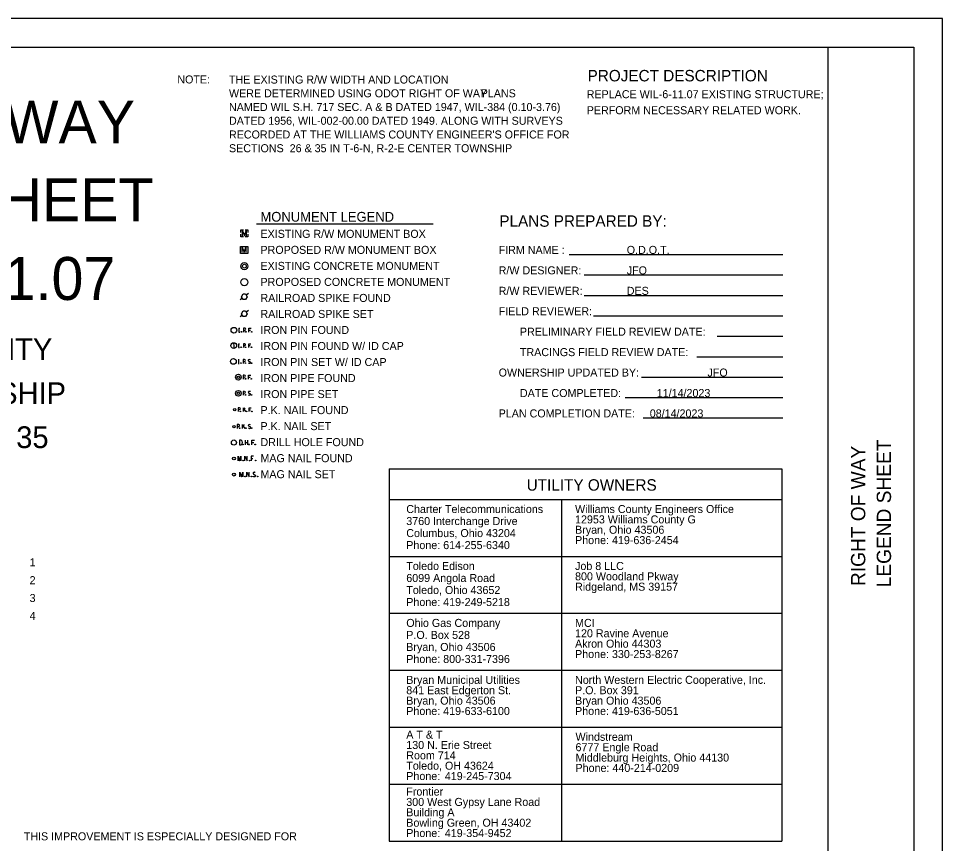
# Model space of a CAD drawing. Extents: x 0 to 34, y 0 to 22.
# Drawn here: x 17.84 to 34, y 7.58 to 22 of the extents above; entities that cross this region are included whole.
import ezdxf

# ---------------------------------------------------------------- set-up
doc = ezdxf.new("R2010")
doc.units = 0
for name, color, linetype in [('SH_Border', 7, 'Continuous'), ('SH_Cut_Line', 7, 'Continuous'), ('SH_Data', 7, 'Continuous'), ('SH_Text', 7, 'Continuous'), ('SV_P_Control_Cells_Set', 7, 'Continuous'), ('SV_X_Control_Cells_Found', 7, 'Continuous')]:
    doc.layers.add(name, color=color, linetype=linetype)

msp = doc.modelspace()

# ---------------------------------------------------------------- linework, layer by layer
at = {"layer": 'SH_Border'}
msp.add_line((32, 0.5), (32, 21.5), dxfattribs=at)
msp.add_lwpolyline([(1.5, 21.5), (33.5, 21.5), (33.5, 0.5), (1.5, 0.5)], close=True, dxfattribs=at)
at = {"layer": 'SH_Cut_Line'}
msp.add_lwpolyline([(0, 0), (34, 0), (34, 22), (0, 22)], close=True, dxfattribs=at)
at = {"layer": 'SH_Text'}
for p, q in [((22.005, 18.412), (25.097, 18.412)), ((21.793, 18.246), (21.793, 18.246)), ((21.788, 17.956), (21.788, 17.956)), ((27.471, 17.876), (31.208, 17.876)), ((27.735, 17.519), (31.208, 17.519)), ((21.866, 17.194), (21.826, 17.164)), ((27.735, 17.162), (31.208, 17.162)), ((21.759, 17.114), (21.719, 17.084)), ((21.759, 16.817), (21.719, 16.787)), ((21.866, 16.897), (21.826, 16.867)), ((27.899, 16.804), (31.208, 16.804)), ((21.694, 16.587), (21.711, 16.587)), ((21.694, 16.587), (21.711, 16.587)), ((21.694, 16.52), (21.711, 16.52)), ((21.703, 16.52), (21.703, 16.587)), ((21.779, 16.555), (21.806, 16.555)), ((21.873, 16.52), (21.873, 16.587)), ((21.873, 16.587), (21.911, 16.587)), ((21.873, 16.554), (21.9, 16.554)), ((30.062, 16.447), (31.208, 16.447)), ((21.607, 16.289), (21.607, 16.252)), ((21.69, 16.317), (21.707, 16.317)), ((21.69, 16.317), (21.707, 16.317)), ((21.69, 16.251), (21.707, 16.251)), ((21.698, 16.251), (21.698, 16.317)), ((21.775, 16.285), (21.802, 16.285)), ((21.869, 16.251), (21.869, 16.317)), ((21.869, 16.317), (21.907, 16.317)), ((21.869, 16.285), (21.896, 16.285)), ((21.686, 16.041), (21.702, 16.041)), ((21.686, 16.041), (21.702, 16.041)), ((21.694, 15.974), (21.694, 16.041)), ((21.771, 16.009), (21.797, 16.009)), ((21.865, 16.017), (21.895, 16.001)), ((29.705, 16.09), (31.208, 16.09)), ((21.686, 15.974), (21.702, 15.974)), ((21.772, 15.733), (21.798, 15.733)), ((21.865, 15.699), (21.865, 15.765)), ((21.865, 15.765), (21.904, 15.765)), ((21.865, 15.733), (21.893, 15.733)), ((28.735, 15.733), (31.208, 15.733)), ((21.772, 15.452), (21.798, 15.452)), ((21.866, 15.46), (21.897, 15.444)), ((28.45, 15.375), (31.208, 15.375)), ((21.777, 15.13), (21.777, 15.197)), ((21.777, 15.154), (21.809, 15.197)), ((21.875, 15.13), (21.875, 15.197)), ((21.875, 15.197), (21.914, 15.197)), ((21.684, 15.165), (21.71, 15.165)), ((21.787, 15.168), (21.815, 15.13)), ((21.875, 15.164), (21.903, 15.164)), ((21.669, 14.872), (21.696, 14.872)), ((21.762, 14.837), (21.762, 14.904)), ((21.762, 14.861), (21.794, 14.904)), ((21.772, 14.875), (21.8, 14.837)), ((21.868, 14.88), (21.898, 14.864)), ((28.765, 15.019), (31.208, 15.019)), ((24.323, 14.128), (31.19, 14.128)), ((24.323, 14.128), (24.323, 7.625)), ((31.19, 14.128), (31.19, 7.625)), ((24.323, 13.597), (31.19, 13.597)), ((27.34, 13.597), (27.34, 7.625)), ((24.323, 12.601), (31.19, 12.601)), ((24.323, 11.606), (31.19, 11.606)), ((24.323, 10.611), (31.19, 10.611)), ((24.323, 9.616), (31.19, 9.616)), ((24.323, 8.621), (31.19, 8.621)), ((24.323, 7.625), (31.19, 7.625))]:
    msp.add_line(p, q, dxfattribs=at)
for points in [[(21.73, 18.262), (21.73, 18.309), (21.777, 18.309)], [(21.762, 18.204), (21.762, 18.288), (21.793, 18.204), (21.823, 18.288), (21.823, 18.204)], [(21.807, 18.309), (21.855, 18.309), (21.855, 18.262)], [(21.777, 18.184), (21.73, 18.184), (21.73, 18.23)], [(21.855, 18.23), (21.855, 18.184), (21.807, 18.184)], [(21.725, 18.018), (21.851, 18.018), (21.851, 17.893), (21.725, 17.893), (21.725, 18.018)], [(21.757, 17.914), (21.757, 17.997), (21.788, 17.914), (21.819, 17.997), (21.819, 17.914)], [(21.806, 16.587), (21.779, 16.587), (21.779, 16.52)], [(21.802, 16.317), (21.775, 16.317), (21.775, 16.251)], [(21.797, 16.041), (21.771, 16.041), (21.771, 15.974)], [(21.798, 15.765), (21.772, 15.765), (21.772, 15.699)], [(21.798, 15.484), (21.772, 15.484), (21.772, 15.417)], [(21.71, 15.197), (21.684, 15.197), (21.684, 15.13)], [(21.696, 14.904), (21.669, 14.904), (21.669, 14.837)]]:
    msp.add_lwpolyline(points, dxfattribs=at)
for points in [[(21.774, 17.189), (21.811, 17.189), (21.841, 17.139), (21.811, 17.089), (21.774, 17.089), (21.744, 17.139)], [(21.774, 16.892), (21.811, 16.892), (21.841, 16.842), (21.811, 16.792), (21.774, 16.792), (21.744, 16.842)]]:
    msp.add_lwpolyline(points, close=True, dxfattribs=at)
for centre, radius in [((21.793, 17.673), 0.0625), ((21.793, 17.673), 0.0333), ((21.793, 17.392), 0.0625), ((21.611, 16.553), 0.05), ((21.743, 16.524), 0.00583), ((21.819, 16.524), 0.00583), ((21.921, 16.524), 0.00583), ((21.607, 16.284), 0.05), ((21.607, 16.311), 0.00667), ((21.738, 16.255), 0.00583), ((21.815, 16.255), 0.00583), ((21.917, 16.255), 0.00583), ((21.602, 16.008), 0.05), ((21.734, 15.979), 0.00583), ((21.811, 15.979), 0.00583), ((21.918, 15.978), 0.00583), ((21.688, 15.732), 0.05), ((21.688, 15.732), 0.0206), ((21.812, 15.703), 0.00583), ((21.914, 15.703), 0.00583), ((21.688, 15.45), 0.05), ((21.688, 15.45), 0.0208), ((21.812, 15.422), 0.00583), ((21.919, 15.421), 0.00583), ((21.624, 15.163), 0.0207), ((21.724, 15.134), 0.00583), ((21.833, 15.134), 0.00583), ((21.924, 15.134), 0.00583), ((21.611, 14.87), 0.0206), ((21.71, 14.842), 0.00583), ((21.821, 14.842), 0.00583), ((21.921, 14.842), 0.00583)]:
    msp.add_circle(centre, radius, dxfattribs=at)
for centre, radius, start, end in [((21.803, 16.571), 0.0162, 278.8803, 81.1197), ((21.799, 16.301), 0.0162, 278.8803, 81.1197), ((21.795, 16.025), 0.0162, 278.8803, 81.1197), ((21.871, 16.027), 0.0118, 126.2587, 236.3675), ((21.881, 16.006), 0.0349, 61.3463, 118.6537), ((21.886, 15.99), 0.0148, 311.4883, 47.9358), ((21.88, 16.002), 0.0276, 223.6695, 304.3963), ((21.796, 15.749), 0.0162, 278.8803, 81.1197), ((21.796, 15.468), 0.0162, 278.8803, 81.1197), ((21.873, 15.47), 0.0118, 126.2587, 236.3675), ((21.881, 15.445), 0.0276, 223.6695, 304.3963), ((21.882, 15.449), 0.0349, 61.3463, 118.6537), ((21.887, 15.433), 0.0148, 311.4883, 47.9358), ((21.708, 15.181), 0.0162, 278.8803, 81.1197), ((21.694, 14.888), 0.0162, 278.8803, 81.1197), ((21.874, 14.89), 0.0118, 126.2587, 236.3675), ((21.884, 14.869), 0.0349, 61.3463, 118.6537), ((21.889, 14.853), 0.0148, 311.4883, 47.9358), ((21.883, 14.865), 0.0276, 223.6695, 304.3963)]:
    msp.add_arc(centre, radius, start, end, dxfattribs=at)
at = {"layer": 'SV_P_Control_Cells_Set'}
for points in [[(21.715, 13.99), (21.715, 14.07), (21.741, 13.99), (21.765, 14.07), (21.765, 13.99)], [(21.834, 13.99), (21.834, 14.07), (21.875, 13.99), (21.875, 14.07)], [(21.983, 14.065), (21.982, 14.066), (21.98, 14.067), (21.975, 14.069), (21.969, 14.07), (21.964, 14.07), (21.963, 14.07), (21.956, 14.068), (21.95, 14.065), (21.946, 14.06), (21.945, 14.055), (21.945, 14.051), (21.946, 14.046), (21.95, 14.041), (21.98, 14.022), (21.983, 14.02), (21.984, 14.017), (21.985, 14.014), (21.985, 14.01), (21.985, 14.006), (21.984, 14.004), (21.983, 14), (21.982, 13.998), (21.981, 13.996), (21.979, 13.994), (21.978, 13.993), (21.975, 13.992), (21.974, 13.991), (21.969, 13.99), (21.961, 13.99), (21.956, 13.992), (21.949, 13.996), (21.945, 14)], [(21.804, 14.001), (21.806, 14.001), (21.808, 14), (21.81, 13.997), (21.81, 13.994), (21.808, 13.992), (21.806, 13.99), (21.804, 13.99), (21.802, 13.992), (21.8, 13.994), (21.8, 13.997), (21.802, 14), (21.804, 14.001)], [(21.914, 14.001), (21.917, 14.001), (21.919, 14), (21.92, 13.997), (21.92, 13.994), (21.919, 13.992), (21.917, 13.99), (21.914, 13.99), (21.913, 13.992), (21.911, 13.994), (21.911, 13.997), (21.913, 14), (21.914, 14.001)], [(22.023, 14.001), (22.026, 14.001), (22.028, 14), (22.029, 13.997), (22.029, 13.994), (22.028, 13.992), (22.026, 13.99), (22.023, 13.99), (22.022, 13.992), (22.02, 13.994), (22.02, 13.997), (22.022, 14), (22.023, 14.001)]]:
    msp.add_lwpolyline(points, dxfattribs=at)
msp.add_circle((21.611, 14.03), 0.0249, dxfattribs=at)
at = {"layer": 'SV_X_Control_Cells_Found'}
for p, q in [((21.811, 14.55), (21.811, 14.63)), ((21.811, 14.59), (21.855, 14.59)), ((21.855, 14.55), (21.855, 14.63)), ((21.924, 14.55), (21.924, 14.63)), ((21.924, 14.63), (21.97, 14.63)), ((21.924, 14.591), (21.956, 14.591))]:
    msp.add_line(p, q, dxfattribs=at)
for points in [[(21.737, 14.63), (21.709, 14.63), (21.709, 14.55), (21.737, 14.55)], [(21.683, 14.27), (21.683, 14.35), (21.708, 14.27), (21.732, 14.35), (21.732, 14.27)], [(21.771, 14.281), (21.774, 14.281), (21.775, 14.279), (21.777, 14.277), (21.777, 14.274), (21.775, 14.271), (21.774, 14.27), (21.771, 14.27), (21.769, 14.271), (21.768, 14.274), (21.768, 14.277), (21.769, 14.279), (21.771, 14.281)], [(21.801, 14.27), (21.801, 14.35), (21.843, 14.27), (21.843, 14.35)], [(21.882, 14.281), (21.885, 14.281), (21.886, 14.279), (21.888, 14.277), (21.888, 14.274), (21.886, 14.271), (21.885, 14.27), (21.882, 14.27), (21.88, 14.271), (21.878, 14.274), (21.878, 14.277), (21.88, 14.279), (21.882, 14.281)], [(21.95, 14.35), (21.912, 14.35), (21.912, 14.27)], [(21.912, 14.311), (21.939, 14.311)], [(21.989, 14.281), (21.992, 14.281), (21.994, 14.279), (21.995, 14.277), (21.995, 14.274), (21.994, 14.271), (21.992, 14.27), (21.989, 14.27), (21.988, 14.271), (21.986, 14.274), (21.986, 14.277), (21.988, 14.279), (21.989, 14.281)]]:
    msp.add_lwpolyline(points, dxfattribs=at)
for centre, radius in [((21.611, 14.59), 0.045), ((21.767, 14.555), 0.007), ((21.874, 14.555), 0.007), ((21.981, 14.555), 0.007), ((21.611, 14.31), 0.0249)]:
    msp.add_circle(centre, radius, dxfattribs=at)
msp.add_arc((21.712, 14.59), 0.0474, 302.5148, 57.4852, dxfattribs=at)

# ---------------------------------------------------------------- texts
at = {"layer": 'SH_Data'}
for s, height, p in [('RIGHT OF WAY', 0.75, (12.527, 19.816)), ('LEGEND SHEET', 0.75, (12.458, 18.457)), ('WIL-US-6-11.07', 0.75, (12.291, 17.082)), ('WILLIAMS COUNTY', 0.38, (13.72, 16.03)), ('CENTER TOWNSHIP', 0.38, (13.706, 15.262)), ('SECTIONS 26 & 35 ', 0.38, (13.879, 14.493)), ('1', 0.14, (18.038, 12.427)), ('2', 0.14, (18.038, 12.115)), ('3', 0.14, (18.038, 11.803)), ('4', 0.14, (18.038, 11.491))]:
    msp.add_text(s, height=height, dxfattribs=at).set_placement(p)
for s, p in [('LEGEND SHEET', (33.1, 12.06)), ('RIGHT OF WAY', (32.65, 12.082))]:
    msp.add_text(s, height=0.25, rotation=90, dxfattribs=at).set_placement(p)
at = {"layer": 'SH_Text'}
for s, height, p in [('NOTE:', 0.14, (20.621, 20.865)), ('THE EXISTING R/W WIDTH AND LOCATION', 0.14, (21.524, 20.863)), ('PROJECT DESCRIPTION', 0.2, (27.794, 20.901)), ('WERE DETERMINED USING ODOT RIGHT OF WAY ', 0.14, (21.524, 20.623)), ('PLANS ', 0.14, (25.925, 20.623)), ('REPLACE WIL-6-11.07 EXISTING STRUCTURE;', 0.14, (27.779, 20.607)), ('NAMED WIL S.H. 717 SEC. A & B DATED 1947, WIL-384 (0.10-3.76)', 0.14, (21.524, 20.383)), ('PERFORM NECESSARY RELATED WORK.', 0.14, (27.779, 20.327)), ('DATED 1956, WIL-002-00.00 DATED 1949. ALONG WITH SURVEYS', 0.14, (21.524, 20.143)), ("RECORDED AT THE WILLIAMS COUNTY ENGINEER'S OFFICE FOR", 0.14, (21.524, 19.903)), ('SECTIONS  26 & 35 IN T-6-N, R-2-E CENTER TOWNSHIP', 0.14, (21.524, 19.663)), ('MONUMENT LEGEND', 0.17, (22.074, 18.45)), ('PLANS PREPARED BY:', 0.2, (26.251, 18.361)), ('EXISTING R/W MONUMENT BOX', 0.14, (22.074, 18.167)), ('PROPOSED R/W MONUMENT BOX', 0.14, (22.074, 17.887)), ('FIRM NAME :', 0.14, (26.239, 17.886)), ('O.D.O.T.', 0.14, (28.479, 17.886)), ('EXISTING CONCRETE MONUMENT', 0.14, (22.074, 17.607)), ('R/W DESIGNER:', 0.14, (26.239, 17.529)), ('JFO', 0.14, (28.479, 17.529)), ('PROPOSED CONCRETE MONUMENT', 0.14, (22.074, 17.327)), ('R/W REVIEWER:', 0.14, (26.239, 17.171)), ('DES', 0.14, (28.479, 17.171)), ('RAILROAD SPIKE FOUND', 0.14, (22.074, 17.047)), ('RAILROAD SPIKE SET', 0.14, (22.074, 16.767)), ('FIELD REVIEWER:', 0.14, (26.239, 16.814)), ('IRON PIN FOUND', 0.14, (22.074, 16.487)), ('PRELIMINARY FIELD REVIEW DATE:', 0.14, (26.611, 16.457)), ('IRON PIN FOUND W/ ID CAP', 0.14, (22.074, 16.207)), ('TRACINGS FIELD REVIEW DATE:', 0.14, (26.611, 16.1)), ('IRON PIN SET W/ ID CAP', 0.14, (22.074, 15.927)), ('OWNERSHIP UPDATED BY:                       JFO', 0.14, (26.239, 15.743)), ('IRON PIPE FOUND', 0.14, (22.074, 15.647)), ('DATE COMPLETED:            11/14/2023', 0.14, (26.611, 15.385)), ('IRON PIPE SET', 0.14, (22.074, 15.367)), ('P.K. NAIL FOUND', 0.14, (22.074, 15.087)), ('PLAN COMPLETION DATE:     08/14/2023', 0.14, (26.239, 15.029)), ('P.K. NAIL SET', 0.14, (22.074, 14.807)), ('DRILL HOLE FOUND', 0.14, (22.074, 14.527)), ('MAG NAIL FOUND', 0.14, (22.074, 14.247)), ('MAG NAIL SET', 0.14, (22.074, 13.967)), ('UTILITY OWNERS', 0.2, (26.729, 13.749)), ('Charter Telecommunications', 0.14, (24.624, 13.358)), ('Williams County Engineers Office', 0.14, (27.575, 13.358)), ('3760 Interchange Drive', 0.14, (24.624, 13.148)), ('12953 Williams County G', 0.14, (27.575, 13.177)), ('Bryan, Ohio 43506', 0.14, (27.575, 12.996)), ('Columbus, Ohio 43204', 0.14, (24.624, 12.938)), ('Phone: 419-636-2454', 0.14, (27.575, 12.815)), ('Phone: 614-255-6340', 0.14, (24.624, 12.728)), ('Toledo Edison', 0.14, (24.624, 12.363)), ('Job 8 LLC', 0.14, (27.575, 12.363)), ('6099 Angola Road', 0.14, (24.624, 12.153)), ('800 Woodland Pkway', 0.14, (27.575, 12.182)), ('Ridgeland, MS 39157', 0.14, (27.575, 12.001)), ('Toledo, Ohio 43652', 0.14, (24.624, 11.943)), ('Phone: 419-249-5218', 0.14, (24.624, 11.733)), ('Ohio Gas Company', 0.14, (24.624, 11.368)), ('MCI', 0.14, (27.575, 11.368)), ('120 Ravine Avenue', 0.14, (27.575, 11.187)), ('P.O. Box 528', 0.14, (24.624, 11.158)), ('Akron Ohio 44303', 0.14, (27.575, 11.006)), ('Bryan, Ohio 43506', 0.14, (24.624, 10.948)), ('Phone: 800-331-7396', 0.14, (24.624, 10.738)), ('Phone: 330-253-8267', 0.14, (27.575, 10.824)), ('Bryan Municipal Utilities', 0.14, (24.624, 10.373)), ('North Western Electric Cooperative, Inc.', 0.14, (27.575, 10.373)), ('841 East Edgerton St.', 0.14, (24.624, 10.192)), ('P.O. Box 391', 0.14, (27.575, 10.192)), ('Bryan, Ohio 43506', 0.14, (24.624, 10.01)), ('Bryan Ohio 43506', 0.14, (27.575, 10.01)), ('Phone: 419-633-6100', 0.14, (24.624, 9.829)), ('Phone: 419-636-5051', 0.14, (27.575, 9.829)), ('A T & T', 0.14, (24.624, 9.416)), ('130 N. Erie Street', 0.14, (24.624, 9.235)), ('Windstream', 0.14, (27.583, 9.378)), ('6777 Engle Road', 0.14, (27.583, 9.196)), ('Room 714 ', 0.14, (24.624, 9.054)), ('Middleburg Heights, Ohio 44130', 0.14, (27.583, 9.015)), ('Toledo, OH 43624', 0.14, (24.624, 8.873)), ('Phone: 440-214-0209', 0.14, (27.583, 8.834)), ('Phone: ', 0.14, (24.624, 8.692)), ('419-245-7304', 0.14, (25.298, 8.692)), ('Frontier ', 0.14, (24.624, 8.421)), ('300 West Gypsy Lane Road ', 0.14, (24.624, 8.24)), ('Building A ', 0.14, (24.624, 8.059)), ('Bowling Green, OH 43402 ', 0.14, (24.624, 7.877)), ('THIS IMPROVEMENT IS ESPECIALLY DESIGNED FOR', 0.14, (17.936, 7.639)), ('Phone: ', 0.14, (24.624, 7.696)), ('419-354-9452', 0.14, (25.298, 7.696))]:
    msp.add_text(s, height=height, dxfattribs=at).set_placement(p)

doc.saveas('drawing.dxf')
